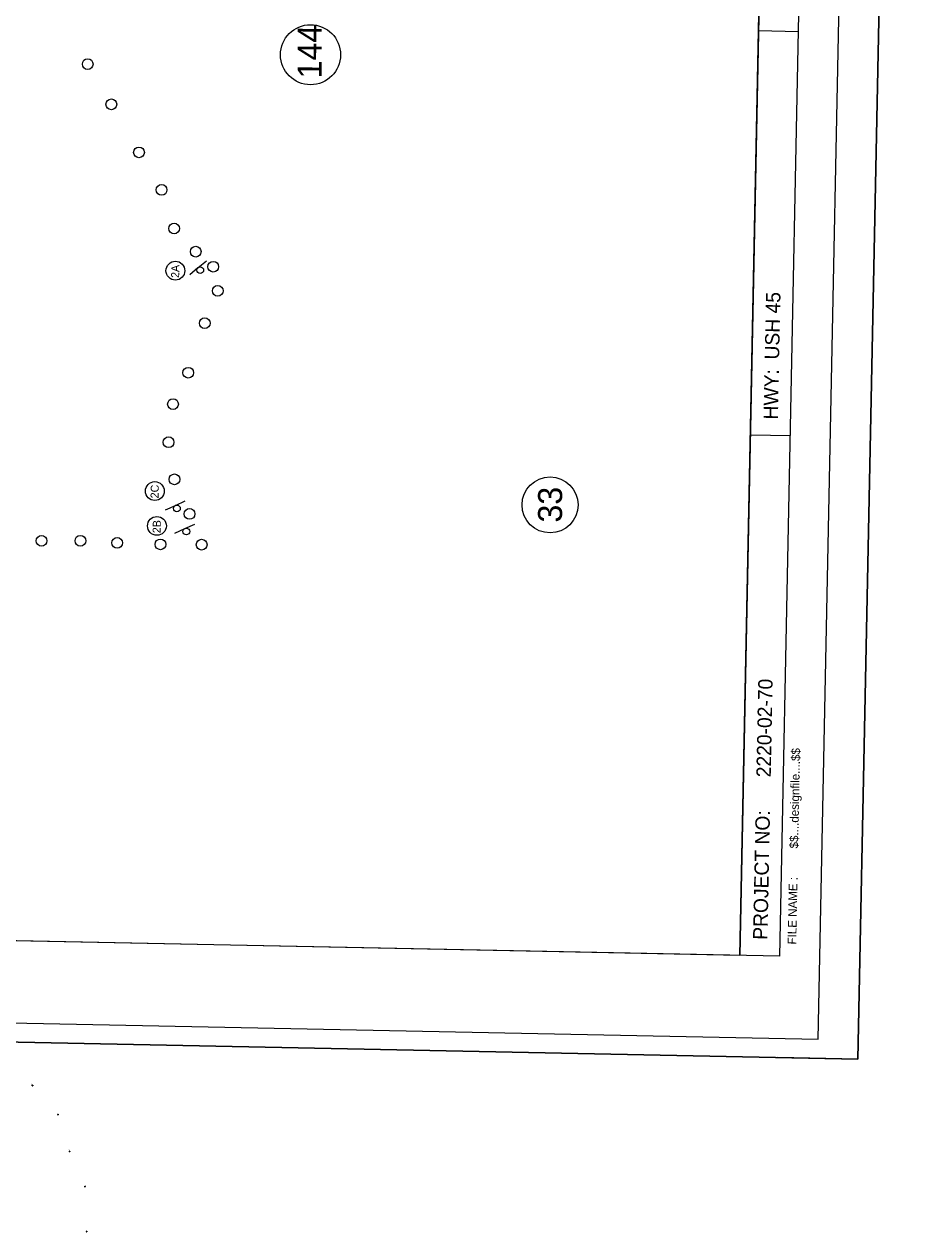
# Model space of a CAD drawing. Extents: x 327762 to 372975, y 127949 to 220470.
# Drawn here: x 359108 to 372975, y 174730 to 193585 of the extents above; entities that cross this region are included whole.
import ezdxf

# ---------------------------------------------------------------- set-up
doc = ezdxf.new("R2010")
doc.units = 0
for name, color, linetype in [('CA-TEXT', 7, 'Continuous'), ('CE-TOPO-CONC-SLAB', 7, 'Continuous'), ('E_SOIL_BORE1 [KAPUR_CADDS_LEVELS]', 7, 'Continuous'), ('E_SOIL_BORE2 [KAPUR_CADDS_LEVELS]', 7, 'Continuous'), ('GSBWFILL', 7, 'Continuous'), ('GSCOLORFILL', 7, 'Continuous'), ('P_MARK', 7, 'Continuous'), ('PLT_Sheet_Border', 7, 'Continuous'), ('PLT_Sheet_Info', 7, 'Continuous'), ('SIGNS-POLES', 7, 'Continuous')]:
    doc.layers.add(name, color=color, linetype=linetype)

msp = doc.modelspace()

# ---------------------------------------------------------------- linework, layer by layer
at = {"layer": 'CA-TEXT'}
for p, q in [((363577, 193107), (363577, 193107)), ((367314, 186079), (367314, 186079))]:
    msp.add_line(p, q, dxfattribs=at)
for centre, radius in [((363577, 193107), 469), ((361468, 189736), 147), ((367314, 186079), 437), ((361147, 186295), 147), ((361180, 185751), 147)]:
    msp.add_circle(centre, radius, dxfattribs=at)
at = {"layer": 'CE-TOPO-CONC-SLAB'}
for centre in [(360100, 192961), (360469, 192333), (360900, 191583), (361253, 190997), (361448, 190395), (361785, 190033), (362059, 189798), (362129, 189421), (361926, 188916), (361669, 188143), (361431, 187653), (361362, 187057), (361453, 186478), (361689, 185938), (359380, 185518), (359986, 185519), (360560, 185486), (361235, 185463), (361878, 185458)]:
    msp.add_circle(centre, 83.7, dxfattribs=at)
at = {"layer": 'GSBWFILL'}
msp.add_lwpolyline([(344626, 177980), (345482, 220470), (372975, 219916), (372119, 177427)], close=True, dxfattribs=at)
at = {"layer": 'GSCOLORFILL'}
msp.add_lwpolyline([(345907, 179536), (346513, 209608), (364425, 209247), (364381, 206427), (370825, 206298), (370277, 179045)], close=True, dxfattribs=at)
at = {"layer": 'P_MARK'}
for p, q in [((359233, 177015), (359243, 177015)), ((359238, 177020), (359238, 177010)), ((359630, 176562), (359640, 176562)), ((359635, 176567), (359635, 176557)), ((359813, 175986), (359823, 175986)), ((359818, 175991), (359818, 175981)), ((360052, 175436), (360062, 175436)), ((360057, 175441), (360057, 175431)), ((360078, 174735), (360088, 174735)), ((360083, 174740), (360083, 174730))]:
    msp.add_line(p, q, dxfattribs=at)
for centre in [(359238, 177015), (359635, 176562), (359818, 175986), (360057, 175436), (360083, 174735)]:
    msp.add_circle(centre, 5, dxfattribs=at)
for centre, radius, start, end in [((359238, 177015), 4.5, 89.9869, 179.9869), ((359238, 177015), 4, 89.9869, 179.9869), ((359238, 177015), 3.5, 89.9869, 179.9869), ((359238, 177015), 3, 89.9869, 179.9869), ((359238, 177015), 2.5, 89.9869, 179.9869), ((359238, 177015), 2, 89.9869, 179.9869), ((359238, 177015), 1.5, 89.9869, 179.9869), ((359238, 177015), 1, 89.9869, 179.9869), ((359238, 177015), 0.5, 89.9869, 179.9869), ((359238, 177015), 4.5, 269.9869, 359.9869), ((359238, 177015), 4, 269.9869, 359.9869), ((359238, 177015), 3.5, 269.9869, 359.9869), ((359238, 177015), 3, 269.9869, 359.9869), ((359238, 177015), 2.5, 269.9869, 359.9869), ((359238, 177015), 2, 269.9869, 359.9869), ((359238, 177015), 1.5, 269.9869, 359.9869), ((359238, 177015), 1, 269.9869, 359.9869), ((359238, 177015), 0.5, 269.9869, 359.9869), ((359635, 176562), 4.5, 89.9869, 179.9869), ((359635, 176562), 4, 89.9869, 179.9869), ((359635, 176562), 3.5, 89.9869, 179.9869), ((359635, 176562), 3, 89.9869, 179.9869), ((359635, 176562), 2.5, 89.9869, 179.9869), ((359635, 176562), 2, 89.9869, 179.9869), ((359635, 176562), 1.5, 89.9869, 179.9869), ((359635, 176562), 1, 89.9869, 179.9869), ((359635, 176562), 0.5, 89.9869, 179.9869), ((359635, 176562), 4.5, 269.9869, 359.9869), ((359635, 176562), 4, 269.9869, 359.9869), ((359635, 176562), 3.5, 269.9869, 359.9869), ((359635, 176562), 3, 269.9869, 359.9869), ((359635, 176562), 2.5, 269.9869, 359.9869), ((359635, 176562), 2, 269.9869, 359.9869), ((359635, 176562), 1.5, 269.9869, 359.9869), ((359635, 176562), 1, 269.9869, 359.9869), ((359635, 176562), 0.5, 269.9869, 359.9869), ((359818, 175986), 4.5, 89.9869, 179.9869), ((359818, 175986), 4, 89.9869, 179.9869), ((359818, 175986), 3.5, 89.9869, 179.9869), ((359818, 175986), 3, 89.9869, 179.9869), ((359818, 175986), 2.5, 89.9869, 179.9869), ((359818, 175986), 2, 89.9869, 179.9869), ((359818, 175986), 1.5, 89.9869, 179.9869), ((359818, 175986), 1, 89.9869, 179.9869), ((359818, 175986), 0.5, 89.9869, 179.9869), ((359818, 175986), 4.5, 269.9869, 359.9869), ((359818, 175986), 4, 269.9869, 359.9869), ((359818, 175986), 3.5, 269.9869, 359.9869), ((359818, 175986), 3, 269.9869, 359.9869), ((359818, 175986), 2.5, 269.9869, 359.9869), ((359818, 175986), 2, 269.9869, 359.9869), ((359818, 175986), 1.5, 269.9869, 359.9869), ((359818, 175986), 1, 269.9869, 359.9869), ((359818, 175986), 0.5, 269.9869, 359.9869), ((360057, 175436), 4.5, 89.9869, 179.9869), ((360057, 175436), 4, 89.9869, 179.9869), ((360057, 175436), 3.5, 89.9869, 179.9869), ((360057, 175436), 3, 89.9869, 179.9869), ((360057, 175436), 2.5, 89.9869, 179.9869), ((360057, 175436), 2, 89.9869, 179.9869), ((360057, 175436), 1.5, 89.9869, 179.9869), ((360057, 175436), 1, 89.9869, 179.9869), ((360057, 175436), 4.5, 269.9869, 359.9869), ((360057, 175436), 4, 269.9869, 359.9869), ((360057, 175436), 3.5, 269.9869, 359.9869), ((360057, 175436), 3, 269.9869, 359.9869), ((360057, 175436), 2.5, 269.9869, 359.9869), ((360057, 175436), 2, 269.9869, 359.9869), ((360057, 175436), 1.5, 269.9869, 359.9869), ((360057, 175436), 1, 269.9869, 359.9869), ((360057, 175436), 0.5, 269.9869, 359.9869), ((360057, 175436), 0.5, 89.9869, 179.9869), ((360083, 174735), 4.5, 89.9869, 179.9869), ((360083, 174735), 4, 89.9869, 179.9869), ((360083, 174735), 3.5, 89.9869, 179.9869), ((360083, 174735), 3, 89.9869, 179.9869), ((360083, 174735), 2.5, 89.9869, 179.9869), ((360083, 174735), 2, 89.9869, 179.9869), ((360083, 174735), 1.5, 89.9869, 179.9869), ((360083, 174735), 1, 89.9869, 179.9869), ((360083, 174735), 0.5, 89.9869, 179.9869), ((360083, 174735), 4.5, 269.9869, 359.9869), ((360083, 174735), 4, 269.9869, 359.9869), ((360083, 174735), 3.5, 269.9869, 359.9869), ((360083, 174735), 3, 269.9869, 359.9869), ((360083, 174735), 2.5, 269.9869, 359.9869), ((360083, 174735), 2, 269.9869, 359.9869), ((360083, 174735), 1.5, 269.9869, 359.9869), ((360083, 174735), 1, 269.9869, 359.9869), ((360083, 174735), 0.5, 269.9869, 359.9869)]:
    msp.add_arc(centre, radius, start, end, dxfattribs=at)
at = {"layer": 'PLT_Sheet_Border'}
for points in [[(372119, 177427), (372975, 219916), (345482, 220470), (344626, 177980)], [(371500, 177739), (372334, 219104), (346090, 219633), (345257, 178268)]]:
    msp.add_lwpolyline(points, close=True, dxfattribs=at)
at = {"layer": 'PLT_Sheet_Info'}
for p, q in [((370277, 179045), (371069, 218411)), ((370901, 179033), (371694, 218398)), ((371192, 193467), (370567, 193479)), ((371065, 187156), (370440, 187168)), ((370901, 179033), (345907, 179536)), ((372119, 177427), (372144, 178676)), ((372119, 177427), (370870, 177452))]:
    msp.add_line(p, q, dxfattribs=at)
at = {"layer": 'SIGNS-POLES'}
for p, q in [((361822, 189783), (361951, 189891)), ((361691, 189674), (361820, 189783)), ((361469, 186071), (361623, 186141)), ((361314, 186002), (361468, 186072)), ((361616, 185710), (361770, 185779)), ((361461, 185640), (361615, 185710))]:
    msp.add_line(p, q, dxfattribs=at)
for centre in [(361856, 189745), (361492, 186025), (361639, 185663)]:
    msp.add_circle(centre, 52.2, dxfattribs=at)

# ---------------------------------------------------------------- texts
at = {"layer": 'CA-TEXT'}
for s, height, rotation, p in [('144', 375, 89.767, (363748, 192737)), ('2A', 125, 88.8468, (361526, 189621)), ('2C', 125, 88.8468, (361205, 186180)), ('33', 375, 89.767, (367501, 185803)), ('2B', 125, 88.8468, (361237, 185636))]:
    msp.add_text(s, height=height, rotation=rotation, dxfattribs=at).set_placement(p)
at = {"layer": 'E_SOIL_BORE1 [KAPUR_CADDS_LEVELS]'}
for s, p in [('B83', (359239, 177024)), ('B84', (359637, 176571)), ('B81', (359820, 175994))]:
    msp.add_text(s, height=10, rotation=118.6843, dxfattribs=at).set_placement(p)
at = {"layer": 'E_SOIL_BORE2 [KAPUR_CADDS_LEVELS]'}
for s, p in [('B81', (359822, 175993)), ('B82', (360062, 175443)), ('B79', (360088, 174741))]:
    msp.add_text(s, height=10, rotation=87.2646, dxfattribs=at).set_placement(p)
at = {"layer": 'PLT_Sheet_Info'}
for s, height, p in [('USH 45         ', 224.99, (370889, 188347)), ('HWY:', 225, (370870, 187410)), ('2220-02-70', 225, (370758, 181824)), ('$$....designfile....$$', 134.99, (371185, 180715)), ('PROJECT NO:', 224.99, (370706, 179287)), ('FILE NAME :', 134.99, (371155, 179215))]:
    msp.add_text(s, height=height, rotation=88.8462, dxfattribs=at).set_placement(p)

doc.saveas('drawing.dxf')
